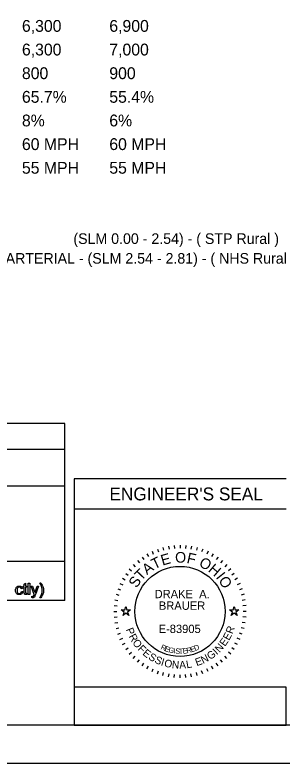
# Model space of a CAD drawing. Extents: x -10.1 to 68, y -9.5 to 29.2.
# Drawn here: x 6.57 to 10.1, y 0 to 9.87 of the extents above; entities that cross this region are included whole.
import ezdxf

# ---------------------------------------------------------------- set-up
doc = ezdxf.new("R2010")
doc.units = 0
for name, color, linetype in [('Default', 7, 'Continuous'), ('SH_Border', 7, 'Continuous'), ('SH_Cut_Line', 7, 'Continuous'), ('SH_Data', 7, 'Continuous'), ('SH_Text', 7, 'Continuous')]:
    doc.layers.add(name, color=color, linetype=linetype)

msp = doc.modelspace()

# ---------------------------------------------------------------- linework, layer by layer
at = {"layer": 'Default'}
for points in [[(7.9736, 2.02), (8.0205, 2.02), (8.035, 2.0645), (8.0495, 2.02), (8.0964, 2.02), (8.0585, 1.9924), (8.073, 1.9478), (8.035, 1.9754), (7.997, 1.9478), (8.0115, 1.9924)], [(9.4036, 2.02), (9.4505, 2.02), (9.465, 2.0645), (9.4795, 2.02), (9.5264, 2.02), (9.4885, 1.9924), (9.503, 1.9478), (9.465, 1.9754), (9.427, 1.9478), (9.4415, 1.9924)]]:
    msp.add_lwpolyline(points, close=True, dxfattribs=at)
at = {"layer": 'SH_Border'}
msp.add_lwpolyline([(1.5, 21.5), (33.5, 21.5), (33.5, 0.5), (1.5, 0.5)], close=True, dxfattribs=at)
at = {"layer": 'SH_Cut_Line'}
msp.add_lwpolyline([(0, 0), (34, 0), (34, 22), (0, 22)], close=True, dxfattribs=at)
at = {"layer": 'SH_Data'}
for p, q in [((7.2275, 4.4803), (2.9775, 4.4803)), ((7.2275, 2.1428), (7.2275, 4.4803)), ((2.9775, 4.1387), (7.2275, 4.1387)), ((2.9775, 3.6553), (7.2275, 3.6553)), ((10.15, 3.75), (7.35, 3.75)), ((7.35, 3.75), (7.35, 0.5)), ((10.15, 3.35), (7.35, 3.35)), ((8.6737, 2.8717), (8.6772, 2.8318)), ((8.75, 2.875), (8.75, 2.835)), ((8.8263, 2.8717), (8.8228, 2.8318)), ((8.3802, 2.793), (8.3971, 2.7568)), ((8.4507, 2.8222), (8.4644, 2.7846)), ((8.5235, 2.8452), (8.5339, 2.8065)), ((8.5981, 2.8617), (8.605, 2.8223)), ((8.9019, 2.8617), (8.895, 2.8223)), ((8.9765, 2.8452), (8.9661, 2.8065)), ((9.0493, 2.8222), (9.0356, 2.7846)), ((9.1198, 2.793), (9.1029, 2.7568)), ((8.1876, 2.6703), (8.2133, 2.6396)), ((8.2481, 2.7168), (8.2711, 2.684)), ((8.3125, 2.7578), (8.3325, 2.7231)), ((9.1875, 2.7578), (9.1675, 2.7231)), ((9.2519, 2.7168), (9.2289, 2.684)), ((9.3124, 2.6703), (9.2867, 2.6396)), ((7.2275, 2.6607), (2.9775, 2.6607)), ((8.1313, 2.6187), (8.1596, 2.5904)), ((9.3687, 2.6187), (9.3404, 2.5904)), ((8.0332, 2.5019), (8.066, 2.4789)), ((8.0797, 2.5624), (8.1104, 2.5367)), ((9.4203, 2.5624), (9.3896, 2.5367)), ((9.4668, 2.5019), (9.434, 2.4789)), ((7.957, 2.3698), (7.9932, 2.3529)), ((7.9922, 2.4375), (8.0269, 2.4175)), ((9.5078, 2.4375), (9.4731, 2.4175)), ((9.543, 2.3698), (9.5068, 2.3529)), ((7.9278, 2.2993), (7.9654, 2.2856)), ((9.5722, 2.2993), (9.5346, 2.2856)), ((7.9048, 2.2265), (7.9435, 2.2161)), ((9.5952, 2.2265), (9.5565, 2.2161)), ((7.2275, 2.1428), (2.9775, 2.1428)), ((7.8783, 2.0763), (7.9182, 2.0728)), ((7.8883, 2.1519), (7.9277, 2.145)), ((9.6117, 2.1519), (9.5723, 2.145)), ((9.6217, 2.0763), (9.5818, 2.0728)), ((7.875, 2), (7.915, 2)), ((9.625, 2), (9.585, 2)), ((7.8783, 1.9237), (7.9182, 1.9272)), ((9.6217, 1.9237), (9.5818, 1.9272)), ((7.8883, 1.8481), (7.9277, 1.855)), ((7.9048, 1.7735), (7.9435, 1.7839)), ((9.5952, 1.7735), (9.5565, 1.7839)), ((9.6117, 1.8481), (9.5723, 1.855)), ((7.9278, 1.7007), (7.9654, 1.7144)), ((9.5722, 1.7007), (9.5346, 1.7144)), ((7.957, 1.6302), (7.9932, 1.6471)), ((7.9922, 1.5625), (8.0269, 1.5825)), ((9.5078, 1.5625), (9.4731, 1.5825)), ((9.543, 1.6302), (9.5068, 1.6471)), ((8.0332, 1.4981), (8.066, 1.5211)), ((9.4668, 1.4981), (9.434, 1.5211)), ((8.0797, 1.4376), (8.1104, 1.4633)), ((8.1313, 1.3813), (8.1596, 1.4096)), ((9.3687, 1.3813), (9.3404, 1.4096)), ((9.4203, 1.4376), (9.3896, 1.4633)), ((8.1876, 1.3297), (8.2133, 1.3604)), ((8.2481, 1.2832), (8.2711, 1.316)), ((9.2519, 1.2832), (9.2289, 1.316)), ((9.3124, 1.3297), (9.2867, 1.3604)), ((8.3125, 1.2422), (8.3325, 1.2769)), ((8.3802, 1.207), (8.3971, 1.2432)), ((8.4507, 1.1778), (8.4644, 1.2154)), ((8.5235, 1.1548), (8.5339, 1.1935)), ((8.9765, 1.1548), (8.9661, 1.1935)), ((9.0493, 1.1778), (9.0356, 1.2154)), ((9.1198, 1.207), (9.1029, 1.2432)), ((9.1875, 1.2422), (9.1675, 1.2769)), ((8.5981, 1.1383), (8.605, 1.1777)), ((8.6737, 1.1283), (8.6772, 1.1682)), ((8.75, 1.125), (8.75, 1.165)), ((8.8263, 1.1283), (8.8228, 1.1682)), ((8.9019, 1.1383), (8.895, 1.1777)), ((10.15, 0.5), (7.35, 0.5))]:
    msp.add_line(p, q, dxfattribs=at)
msp.add_lwpolyline([(10.15, 0.5), (10.15, 1), (7.35, 1), (7.35, 0.5)], close=True, dxfattribs=at)
msp.add_circle((8.75, 2), 0.595, dxfattribs=at)
at = {"layer": 'SH_Text'}
for points in [[(6.692, 2.2558), (6.692, 2.3185), (6.6784, 2.3185), (6.6784, 2.3328), (6.692, 2.3328), (6.692, 2.3597), (6.7105, 2.3708), (6.7105, 2.3328), (6.7289, 2.3328), (6.7289, 2.3185), (6.7105, 2.3185), (6.7105, 2.2547)], [(6.7465, 2.2239), (6.7465, 2.3741), (6.7649, 2.3741), (6.7649, 2.2239), (6.7465, 2.2239)], [(6.8974, 2.3766), (6.9105, 2.3766)], [(6.6712, 2.3007), (6.6532, 2.298)], [(6.8243, 2.2238), (6.783, 2.3328), (6.8029, 2.3328), (6.8255, 2.2699)], [(6.841, 2.2693), (6.8643, 2.3328), (6.8827, 2.3328), (6.8414, 2.222)], [(6.6548, 2.2638), (6.6729, 2.2613)], [(6.7289, 2.2404), (6.7315, 2.2241)], [(6.7928, 2.1821), (6.7907, 2.1995)], [(6.9105, 2.1798), (6.8974, 2.1798)]]:
    msp.add_lwpolyline(points, dxfattribs=at)
for points in [[(6.8974, 2.1798), (6.9279, 2.2289), (6.9279, 2.2782), (6.9279, 2.2974), (6.9235, 2.3164), (6.92, 2.3317), (6.9138, 2.3459), (6.9098, 2.3551), (6.8974, 2.3766)], [(6.9105, 2.3766), (6.9298, 2.3509), (6.939, 2.325), (6.9469, 2.3026), (6.9469, 2.2783), (6.9469, 2.2506), (6.9363, 2.2248), (6.9257, 2.199), (6.9105, 2.1798)], [(6.6729, 2.2613), (6.67, 2.2427), (6.6577, 2.2321), (6.6455, 2.2215), (6.6277, 2.2215), (6.6053, 2.2215), (6.5917, 2.2361), (6.5782, 2.2507), (6.5782, 2.2779), (6.5782, 2.2955), (6.584, 2.3088), (6.5899, 2.322), (6.6018, 2.3286), (6.6137, 2.3352), (6.6278, 2.3352), (6.6455, 2.3352), (6.6568, 2.3262), (6.668, 2.3172), (6.6712, 2.3007)], [(6.6532, 2.298), (6.6507, 2.309), (6.6442, 2.3145), (6.6377, 2.3201), (6.6285, 2.3201), (6.6146, 2.3201), (6.6059, 2.3101), (6.5972, 2.3001), (6.5972, 2.2784), (6.5972, 2.2565), (6.6056, 2.2466), (6.614, 2.2366), (6.6275, 2.2366), (6.6384, 2.2366), (6.6456, 2.2433), (6.6529, 2.2499), (6.6548, 2.2638)], [(6.8255, 2.2699), (6.8299, 2.258), (6.8334, 2.2448), (6.8366, 2.2572), (6.841, 2.2693)], [(6.7315, 2.2241), (6.7238, 2.2224), (6.7176, 2.2224), (6.7076, 2.2224), (6.7021, 2.2256), (6.6965, 2.2288), (6.6943, 2.234), (6.692, 2.2392), (6.692, 2.2558)], [(6.7105, 2.2547), (6.7105, 2.2468), (6.7114, 2.2445), (6.7124, 2.2423), (6.7146, 2.2409), (6.7168, 2.2396), (6.7209, 2.2396), (6.7239, 2.2396), (6.7289, 2.2404)], [(6.7907, 2.1995), (6.7967, 2.1978), (6.8012, 2.1978), (6.8074, 2.1978), (6.811, 2.1999), (6.8147, 2.2019), (6.8171, 2.2056), (6.8188, 2.2084), (6.8227, 2.2193), (6.8232, 2.2209), (6.8243, 2.2238)], [(6.8414, 2.222), (6.8348, 2.2042), (6.8311, 2.1974), (6.8262, 2.1883), (6.8198, 2.1841), (6.8135, 2.1799), (6.8046, 2.1799), (6.7993, 2.1799), (6.7928, 2.1821)]]:
    msp.add_open_spline(points, degree=3, dxfattribs=at)

# ---------------------------------------------------------------- texts
at = {"layer": 'SH_Data'}
for s, height, p in [('6,300', 0.15597, (6.6621, 9.6465)), ('6,900', 0.15597, (7.816, 9.6465)), ('6,300', 0.15597, (6.6621, 9.3346)), ('7,000', 0.15597, (7.816, 9.3346)), ('800', 0.15597, (6.6621, 9.0226)), ('900', 0.15597, (7.816, 9.0226)), ('65.7%', 0.15597, (6.6621, 8.7107)), ('55.4%', 0.15597, (7.816, 8.7107)), ('8%', 0.15597, (6.6621, 8.3988)), ('6%', 0.15597, (7.816, 8.3988)), ('60 MPH', 0.15597, (6.6621, 8.0869)), ('60 MPH', 0.15597, (7.816, 8.0869)), ('55 MPH', 0.15597, (6.6621, 7.7749)), ('55 MPH', 0.15597, (7.816, 7.7749)), ("ENGINEER'S SEAL", 0.17, (7.8176, 3.465)), ('DRAKE  A.', 0.11, (8.4142, 2.1749)), ('BRAUER', 0.11, (8.4702, 2.0216)), ('E-83905', 0.11, (8.4673, 1.7151))]:
    msp.add_text(s, height=height, dxfattribs=at).set_placement(p)
for s, height, rotation, p in [('E', 0.14, 15.75706, (8.5184, 2.6038)), ('O', 0.14, 359.78119, (8.6847, 2.6443)), ('F', 0.14, 347.43619, (8.8311, 2.6417)), ('T', 0.14, 25.71674, (8.4116, 2.5518)), ('O', 0.14, 332.25863, (8.9898, 2.6015)), ('T', 0.14, 46.4344, (8.2383, 2.3964)), ('A', 0.14, 36.47472, (8.3134, 2.4781)), ('H', 0.14, 319.91363, (9.1132, 2.5361)), ('I', 0.14, 308.36695, (9.2165, 2.4483)), ('S', 0.14, 57.19238, (8.1781, 2.3014)), ('O', 0.14, 303.14906, (9.2521, 2.4089)), ('P', 0.1, 291.49398, (8.0323, 1.7621)), ('R', 0.1, 69.23216, (9.4419, 1.6954)), ('R', 0.1, 298.73106, (8.069, 1.6717)), ('E', 0.1, 61.99508, (9.3976, 1.6098)), ('O', 0.1, 306.46664, (8.1155, 1.5883)), ('N', 0.1, 47.02243, (9.2702, 1.4508)), ('E', 0.1, 54.75801, (9.3433, 1.5314)), ('F', 0.1, 314.7068, (8.1843, 1.4983)), ('E', 0.1, 321.43929, (8.2478, 1.4348)), ('R', 0.07, 334.48695, (8.4875, 1.5051)), ('E', 0.07, 341.03996, (8.5406, 1.4801)), ('G', 0.07, 347.47515, (8.5914, 1.4618)), ('I', 0.07, 353.78581, (8.6591, 1.4468)), ('S', 0.07, 356.89262, (8.6858, 1.4429)), ('T', 0.07, 3.00609, (8.7357, 1.4387)), ('E', 0.07, 6.01169, (8.7889, 1.4412)), ('R', 0.07, 11.91844, (8.8425, 1.4474)), ('E', 0.07, 17.68363, (8.8998, 1.4602)), ('D', 0.07, 23.30524, (8.951, 1.477)), ('G', 0.1, 35.04687, (9.1481, 1.357)), ('I', 0.1, 43.28703, (9.2368, 1.4214)), ('S', 0.1, 328.67637, (8.3243, 1.3752)), ('S', 0.1, 335.91345, (8.4064, 1.3266)), ('I', 0.1, 343.15053, (8.4906, 1.2897)), ('E', 0.1, 20.07421, (8.9712, 1.277)), ('N', 0.1, 27.31129, (9.0545, 1.3075)), ('O', 0.1, 346.88592, (8.5339, 1.2751)), ('N', 0.1, 355.12608, (8.6388, 1.2517)), ('A', 0.1, 2.86166, (8.7423, 1.2437)), ('L', 0.1, 10.09874, (8.8394, 1.249))]:
    msp.add_text(s, height=height, rotation=rotation, dxfattribs=at).set_placement(p)
at = {"layer": 'SH_Text'}
for s, p in [('(Other Federal-Aide Highway) - MINOR ARTERIAL -                   (SLM 0.00 - 2.54) - ( STP Rural )', (1.9944, 6.8483)), ('(NHS Non-Interstate) -                OTHER PRINCIPAL ARTERIAL - (SLM 2.54 - 2.81) - ( NHS Rural )', (1.9944, 6.5882))]:
    msp.add_text(s, height=0.14, dxfattribs=at).set_placement(p)

doc.saveas('drawing.dxf')
